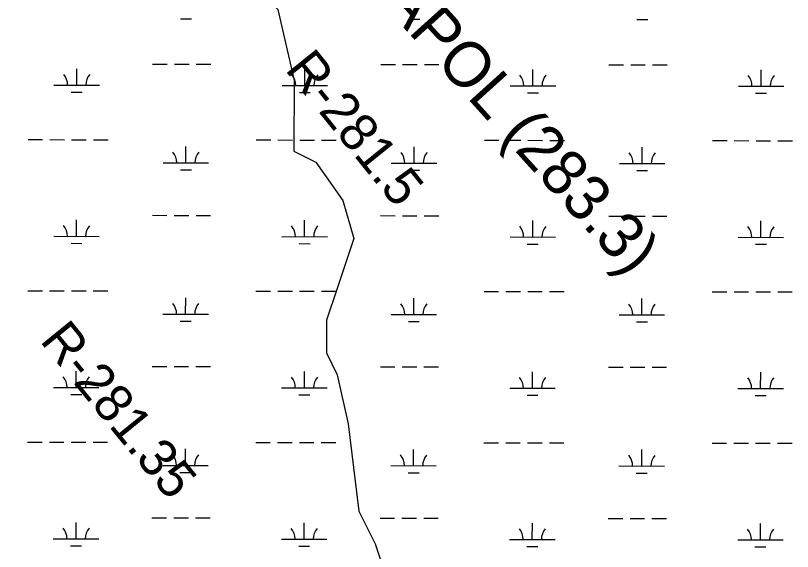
# Model space of a CAD drawing. Extents: x 3208593 to 3246461, y 812903 to 838290.
# Drawn here: x 3214527 to 3216236, y 828025 to 829204 of the extents above; entities that cross this region are included whole.
import ezdxf

# ---------------------------------------------------------------- set-up
doc = ezdxf.new("R2010")
doc.units = 0
for name, color, linetype in [('V-CHAN-NAID', 7, 'Continuous'), ('V-RIVR-RANG-IDEN', 7, 'Continuous'), ('V-TOPO-SHOR', 7, 'Continuous'), ('V-WETL-SWMP', 7, 'Continuous')]:
    doc.layers.add(name, color=color, linetype=linetype)

msp = doc.modelspace()

# ---------------------------------------------------------------- linework, layer by layer
at = {"layer": 'V-TOPO-SHOR'}
msp.add_lwpolyline([(3214492.6, 829290), (3214576.6, 829349.9), (3214684.6, 829397.7), (3214792.5, 829409.5), (3214912.3, 829325.4), (3214960.2, 829313.3), (3215044.1, 829277.2), (3215104, 829217.2), (3215139.7, 829061.3), (3215139.5, 828905.4), (3215187.4, 828881.3), (3215247.3, 828797.3), (3215271.1, 828713.3), (3215235, 828605.5), (3215210.9, 828533.6), (3215210.8, 828461.6), (3215234.7, 828413.6), (3215258.5, 828305.7), (3215282.2, 828113.8), (3215318.1, 828041.8), (3215365.9, 827897.8)], dxfattribs=at)
at = {"layer": 'V-WETL-SWMP'}
for p, q in [((3214890.2, 829197), (3214914.2, 829196.9)), ((3215392.2, 829196.2), (3215416.2, 829196.2)), ((3215894.1, 829195.5), (3215918.1, 829195.5)), ((3214828.7, 829097.1), (3214860.7, 829097)), ((3214876.7, 829097), (3214908.7, 829096.9)), ((3214924.7, 829096.9), (3214956.7, 829096.9)), ((3215330.6, 829096.3), (3215362.6, 829096.3)), ((3215378.6, 829096.3), (3215410.6, 829096.2)), ((3215426.6, 829096.2), (3215458.6, 829096.1)), ((3215832.5, 829095.6), (3215864.5, 829095.6)), ((3215880.5, 829095.5), (3215912.5, 829095.5)), ((3215928.5, 829095.5), (3215960.5, 829095.4)), ((3214661.6, 829050.9), (3214661.6, 829086.9)), ((3215163.5, 829050.1), (3215163.5, 829086.1)), ((3215665.4, 829049.4), (3215665.4, 829085.4)), ((3216167.3, 829048.7), (3216167.3, 829084.7)), ((3214611.6, 829050.9), (3214711.6, 829050.8)), ((3215113.5, 829050.2), (3215213.5, 829050.1)), ((3215615.4, 829049.5), (3215715.4, 829049.3)), ((3216117.3, 829048.8), (3216217.3, 829048.6)), ((3214649.5, 829035.5), (3214673.5, 829035.4)), ((3215151.4, 829034.7), (3215175.4, 829034.7)), ((3215653.4, 829034), (3215677.4, 829034)), ((3216155.3, 829033.3), (3216179.3, 829033.2)), ((3214554.5, 828931), (3214586.5, 828930.9)), ((3214602.5, 828930.9), (3214634.5, 828930.8)), ((3214650.5, 828930.8), (3214682.5, 828930.8)), ((3214698.5, 828930.7), (3214730.5, 828930.7)), ((3215056.4, 828930.2), (3215088.4, 828930.2)), ((3215104.4, 828930.2), (3215136.4, 828930.1)), ((3215152.4, 828930.1), (3215184.4, 828930)), ((3215200.4, 828930), (3215232.4, 828930)), ((3215558.4, 828929.5), (3215590.4, 828929.4)), ((3215606.4, 828929.4), (3215638.4, 828929.4)), ((3215654.4, 828929.4), (3215686.4, 828929.3)), ((3215702.4, 828929.3), (3215734.4, 828929.2)), ((3216060.3, 828928.8), (3216092.3, 828928.7)), ((3216108.3, 828928.7), (3216140.3, 828928.6)), ((3216156.3, 828928.6), (3216188.3, 828928.6)), ((3216204.3, 828928.6), (3216236.3, 828928.5)), ((3214901.8, 828879.7), (3214901.8, 828915.7)), ((3215403.7, 828879), (3215403.7, 828915)), ((3215905.6, 828878.2), (3215905.7, 828914.2)), ((3214851.8, 828879.8), (3214951.8, 828879.6)), ((3215353.7, 828879.1), (3215453.7, 828878.9)), ((3215855.6, 828878.3), (3215955.6, 828878.2)), ((3214889.8, 828864.3), (3214913.8, 828864.3)), ((3215391.7, 828863.6), (3215415.7, 828863.5)), ((3215893.6, 828862.8), (3215917.6, 828862.8)), ((3214661.1, 828718.2), (3214661.1, 828754.2)), ((3214828.2, 828764.4), (3214860.2, 828764.3)), ((3214876.2, 828764.3), (3214908.2, 828764.3)), ((3214924.2, 828764.2), (3214956.2, 828764.2)), ((3215163, 828717.5), (3215163, 828753.5)), ((3215330.1, 828763.7), (3215362.1, 828763.6)), ((3215378.1, 828763.6), (3215410.1, 828763.5)), ((3215426.1, 828763.5), (3215458.1, 828763.5)), ((3215664.9, 828716.7), (3215664.9, 828752.7)), ((3215832, 828762.9), (3215864, 828762.9)), ((3215880, 828762.9), (3215912, 828762.8)), ((3215928, 828762.8), (3215960, 828762.7)), ((3216166.8, 828716), (3216166.9, 828752)), ((3214611.1, 828718.3), (3214711.1, 828718.1)), ((3215113, 828717.5), (3215213, 828717.4)), ((3214649.1, 828702.8), (3214673.1, 828702.7)), ((3215151, 828702.1), (3215175, 828702)), ((3215614.9, 828716.8), (3215714.9, 828716.7)), ((3215652.9, 828701.3), (3215676.9, 828701.3)), ((3216116.8, 828716.1), (3216216.8, 828715.9)), ((3216154.8, 828700.6), (3216178.8, 828700.6)), ((3214554.1, 828598.3), (3214586.1, 828598.2)), ((3214602.1, 828598.2), (3214634.1, 828598.2)), ((3214650.1, 828598.1), (3214682.1, 828598.1)), ((3214698.1, 828598.1), (3214730.1, 828598)), ((3214901.3, 828547), (3214901.4, 828583)), ((3215056, 828597.6), (3215088, 828597.5)), ((3215104, 828597.5), (3215136, 828597.4)), ((3215152, 828597.4), (3215184, 828597.4)), ((3215200, 828597.3), (3215232, 828597.3)), ((3215403.2, 828546.3), (3215403.3, 828582.3)), ((3215557.9, 828596.8), (3215589.9, 828596.8)), ((3215605.9, 828596.8), (3215637.9, 828596.7)), ((3215653.9, 828596.7), (3215685.9, 828596.6)), ((3215701.9, 828596.6), (3215733.9, 828596.6)), ((3215905.1, 828545.6), (3215905.2, 828581.6)), ((3216059.8, 828596.1), (3216091.8, 828596)), ((3216107.8, 828596), (3216139.8, 828596)), ((3216155.8, 828596), (3216187.8, 828595.9)), ((3216203.8, 828595.9), (3216235.8, 828595.8)), ((3214851.3, 828547.1), (3214951.3, 828547)), ((3214889.3, 828531.6), (3214913.3, 828531.6)), ((3215353.2, 828546.4), (3215453.2, 828546.2)), ((3215391.2, 828530.9), (3215415.2, 828530.9)), ((3215855.1, 828545.6), (3215955.1, 828545.5)), ((3215893.1, 828530.2), (3215917.1, 828530.1)), ((3214827.7, 828431.7), (3214859.7, 828431.7)), ((3214875.7, 828431.6), (3214907.7, 828431.6)), ((3214923.7, 828431.6), (3214955.7, 828431.5)), ((3215329.6, 828431), (3215361.6, 828430.9)), ((3215377.6, 828430.9), (3215409.6, 828430.9)), ((3215425.6, 828430.8), (3215457.6, 828430.8)), ((3215831.5, 828430.2), (3215863.5, 828430.2)), ((3215879.5, 828430.2), (3215911.5, 828430.1)), ((3215927.5, 828430.1), (3215959.5, 828430.1)), ((3214660.6, 828385.5), (3214660.6, 828421.5)), ((3215162.5, 828384.8), (3215162.6, 828420.8)), ((3215664.4, 828384.1), (3215664.5, 828420.1)), ((3216166.3, 828383.3), (3216166.4, 828419.3)), ((3214610.6, 828385.6), (3214710.6, 828385.4)), ((3215112.5, 828384.9), (3215212.5, 828384.7)), ((3215614.4, 828384.1), (3215714.4, 828384)), ((3216116.3, 828383.4), (3216216.3, 828383.3)), ((3214648.6, 828370.1), (3214672.6, 828370.1)), ((3215150.5, 828369.4), (3215174.5, 828369.3)), ((3215652.4, 828368.6), (3215676.4, 828368.6)), ((3216154.3, 828367.9), (3216178.3, 828367.9)), ((3214553.6, 828265.6), (3214585.6, 828265.6)), ((3214601.6, 828265.5), (3214633.6, 828265.5)), ((3214649.6, 828265.5), (3214681.6, 828265.4)), ((3214697.6, 828265.4), (3214729.6, 828265.4)), ((3215055.5, 828264.9), (3215087.5, 828264.8)), ((3215103.5, 828264.8), (3215135.5, 828264.8)), ((3215151.5, 828264.7), (3215183.5, 828264.7)), ((3215199.5, 828264.7), (3215231.5, 828264.6)), ((3215557.4, 828264.1), (3215589.4, 828264.1)), ((3215605.4, 828264.1), (3215637.4, 828264)), ((3215653.4, 828264), (3215685.4, 828264)), ((3215701.4, 828263.9), (3215733.4, 828263.9)), ((3216059.3, 828263.4), (3216091.3, 828263.4)), ((3216107.3, 828263.3), (3216139.3, 828263.3)), ((3216155.3, 828263.3), (3216187.3, 828263.2)), ((3216203.3, 828263.2), (3216235.3, 828263.2)), ((3214900.8, 828214.4), (3214900.9, 828250.4)), ((3215402.7, 828213.6), (3215402.8, 828249.6)), ((3215904.6, 828212.9), (3215904.7, 828248.9)), ((3214850.8, 828214.4), (3214950.8, 828214.3)), ((3215352.7, 828213.7), (3215452.7, 828213.6)), ((3215854.6, 828213), (3215954.6, 828212.8)), ((3214888.8, 828198.9), (3214912.8, 828198.9)), ((3215390.7, 828198.2), (3215414.7, 828198.2)), ((3215892.6, 828197.5), (3215916.6, 828197.5)), ((3214660.1, 828052.8), (3214660.2, 828088.8)), ((3214827.2, 828099), (3214859.2, 828099)), ((3214875.2, 828099), (3214907.2, 828098.9)), ((3214923.2, 828098.9), (3214955.2, 828098.8)), ((3215162, 828052.1), (3215162.1, 828088.1)), ((3215329.1, 828098.3), (3215361.1, 828098.3)), ((3215377.1, 828098.2), (3215409.1, 828098.2)), ((3215425.1, 828098.2), (3215457.1, 828098.1)), ((3215663.9, 828051.4), (3215664, 828087.4)), ((3215831.1, 828097.6), (3215863.1, 828097.5)), ((3215879.1, 828097.5), (3215911.1, 828097.5)), ((3215927.1, 828097.4), (3215959.1, 828097.4)), ((3216165.8, 828050.7), (3216165.9, 828086.7)), ((3214610.1, 828052.9), (3214710.1, 828052.8)), ((3215112, 828052.2), (3215212, 828052)), ((3215613.9, 828051.5), (3215713.9, 828051.3)), ((3214648.1, 828037.4), (3214672.1, 828037.4)), ((3215150, 828036.7), (3215174, 828036.7)), ((3215651.9, 828036), (3215675.9, 828035.9)), ((3216115.8, 828050.7), (3216215.8, 828050.6)), ((3216153.8, 828035.2), (3216177.8, 828035.2))]:
    msp.add_line(p, q, dxfattribs=at)
for centre, start, end in [((3214606.3, 829051.4), 359.1448, 40.6885), ((3214716.8, 829051.3), 139.1448, 180.6885), ((3215108.2, 829050.7), 359.1448, 40.6885), ((3215218.7, 829050.5), 139.1448, 180.6885), ((3215610.1, 829050), 359.1448, 40.6885), ((3215720.6, 829049.8), 139.1448, 180.6885), ((3216112, 829049.2), 359.1448, 40.6885), ((3216222.5, 829049.1), 139.1448, 180.6885), ((3214846.5, 828880.3), 359.1448, 40.6885), ((3214957, 828880.1), 139.1448, 180.6885), ((3215348.4, 828879.5), 359.1448, 40.6885), ((3215458.9, 828879.4), 139.1448, 180.6885), ((3215850.4, 828878.8), 359.1448, 40.6885), ((3215960.8, 828878.6), 139.1448, 180.6885), ((3214605.8, 828718.8), 359.1448, 40.6885), ((3214716.3, 828718.6), 139.1448, 180.6885), ((3215107.7, 828718), 359.1448, 40.6885), ((3215218.2, 828717.9), 139.1448, 180.6885), ((3215609.6, 828717.3), 359.1448, 40.6885), ((3215720.1, 828717.1), 139.1448, 180.6885), ((3216111.6, 828716.6), 359.1448, 40.6885), ((3216222, 828716.4), 139.1448, 180.6885), ((3214846.1, 828547.6), 359.1448, 40.6885), ((3214956.5, 828547.4), 139.1448, 180.6885), ((3215348, 828546.9), 359.1448, 40.6885), ((3215458.5, 828546.7), 139.1448, 180.6885), ((3215849.9, 828546.1), 359.1448, 40.6885), ((3215960.4, 828546), 139.1448, 180.6885), ((3214605.4, 828386.1), 359.1448, 40.6885), ((3214715.8, 828385.9), 139.1448, 180.6885), ((3215107.3, 828385.3), 359.1448, 40.6885), ((3215217.7, 828385.2), 139.1448, 180.6885), ((3215609.2, 828384.6), 359.1448, 40.6885), ((3215719.7, 828384.5), 139.1448, 180.6885), ((3216111.1, 828383.9), 359.1448, 40.6885), ((3216221.6, 828383.7), 139.1448, 180.6885), ((3214845.6, 828214.9), 359.1448, 40.6885), ((3214956.1, 828214.8), 139.1448, 180.6885), ((3215347.5, 828214.2), 359.1448, 40.6885), ((3215458, 828214), 139.1448, 180.6885), ((3215849.4, 828213.5), 359.1448, 40.6885), ((3215959.9, 828213.3), 139.1448, 180.6885), ((3214604.9, 828053.4), 359.1448, 40.6885), ((3214715.4, 828053.2), 139.1448, 180.6885), ((3215106.8, 828052.7), 359.1448, 40.6885), ((3215217.3, 828052.5), 139.1448, 180.6885), ((3215608.7, 828051.9), 359.1448, 40.6885), ((3215719.2, 828051.8), 139.1448, 180.6885), ((3216110.6, 828051.2), 359.1448, 40.6885), ((3216221.1, 828051.1), 139.1448, 180.6885)]:
    msp.add_arc(centre, 35.2, start, end, dxfattribs=at)

# ---------------------------------------------------------------- texts
at = {"layer": 'V-CHAN-NAID'}
msp.add_text('SEBASTAPOL (283.3)', height=100, rotation=312.0599, dxfattribs=at).set_placement((3214976, 829625.6))
at = {"layer": 'V-RIVR-RANG-IDEN'}
for s, rotation, p in [('R-281.5', 308.8756, (3215118.2, 829084.9)), ('R-281.35', 309.1271, (3214578.8, 828488.1))]:
    msp.add_text(s, height=83, rotation=rotation, dxfattribs=at).set_placement(p)

doc.saveas('drawing.dxf')
